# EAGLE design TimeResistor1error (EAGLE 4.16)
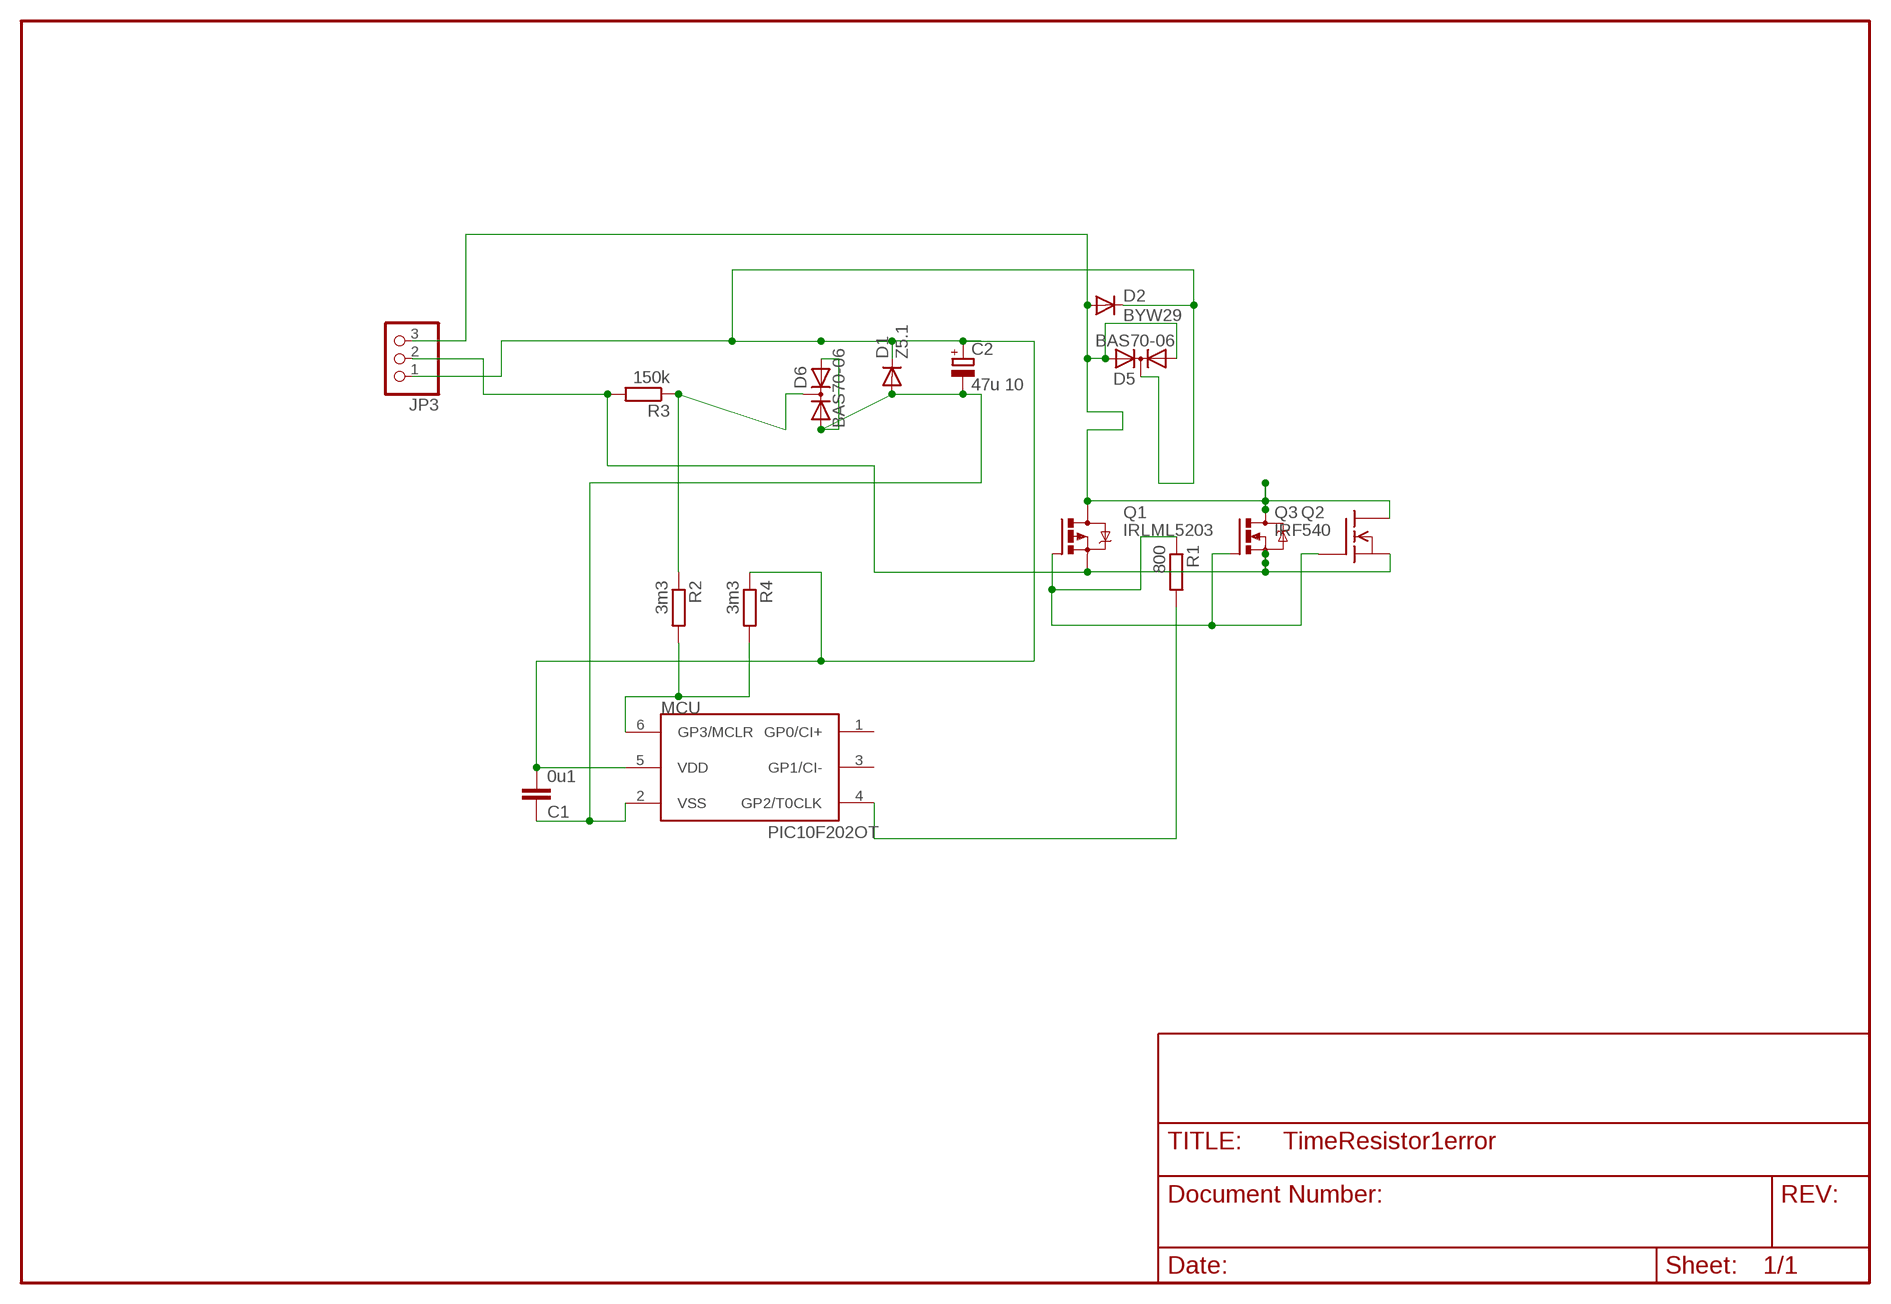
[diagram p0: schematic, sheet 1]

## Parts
C1  0u1  C-EUC1206  [C1206]
C2  47u 10  CPOL-EUSMCD  [SMC_D]
D1  Z5.1  DIODE-MINIMELF  [MINIMELF]
D2  BYW29  [DO220S]
D5  BAS70-06  [SOT23]
D6  BAS70-06  [SOT23]
JP3  PINHD-1X3  [1X03]
MCU  PIC10F202OT  [SOT23-6]
Q1  IRLML5203  [MICRO3]
Q2  N-MOSFET-SO8S  [SO-08]
Q3  IRF540  [TO220]
R1  800  R-EU_R1206  [R1206]
R2  3m3  R-EU_R1206  [R1206]
R3  150k  R-EU_R1206  [R1206]
R4  3m3  R-EU_R1206  [R1206]

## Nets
N$1: Q1.1(G) Q2.4(G) Q3.1(G) R1.1
N$2: D2.A D5.1(A1) D5.2(A2) JP3.3 Q1.3(D) Q2.5(D) Q2.7(D) Q2.8(D) Q3.2(D)
N$11: JP3.2 Q1.2(S) Q2.1(S) Q2.2(S) Q2.3(S) Q3.3(S) R3.2
N$12: MCU.6(GP3/MCLR) R2.2 R4.2
N$14: MCU.4(GP2/T0CLK) R1.2
N$17: D6.3(C) R2.1 R3.1
N$18: C1.1 C2.- D1.A D6.1(A1) D6.2(A2) MCU.2(VSS)
V2CC: C1.2 C2.+ D1.C D2.C D5.3(C) JP3.1 MCU.5(VDD) R4.1
Unconnected: MCU.1(GP0/CI+) MCU.3(GP1/CI-) Q2.6(D)

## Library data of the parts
C1 = rcl:C-EU: CAPACITOR, European symbol
C2 = rcl:CPOL-EU: POLARIZED CAPACITOR, European symbol
D1 = diode:DIODE-: DIODE
D2 = diode:BYW29: DIODE
D5 D6 = diode:BAS70-06: Silicon Schottky Diodes General-purpose diode for high-speed switching
JP3 = pinhead:PINHD-1X3: PIN HEADER
MCU = microchip-3:PIC10F2*: uPC nW 0,25/0,5k Program Flash memory Comparator
Q1 = transistor-power:IRLML5203: HEXFET P-Channel Power MOSFET
Q2 = transistor-power:N-MOSFET-SO8: N-Channel MOSFET Example: FDS7760A; N-Channel Logic Level PowerTrench® MOSFET FDS2572; N-Channel UltraFET® Trench MOSFET Source: www.fairchildsemi.com
Q3 = transistor-fet+irf7201:IRF540: N-Channel Enhancement MOSFET (HEXFET); 100V; 28A; 0,077Ohm
R1-R4 = rcl:R-EU_: RESISTOR, European symbol

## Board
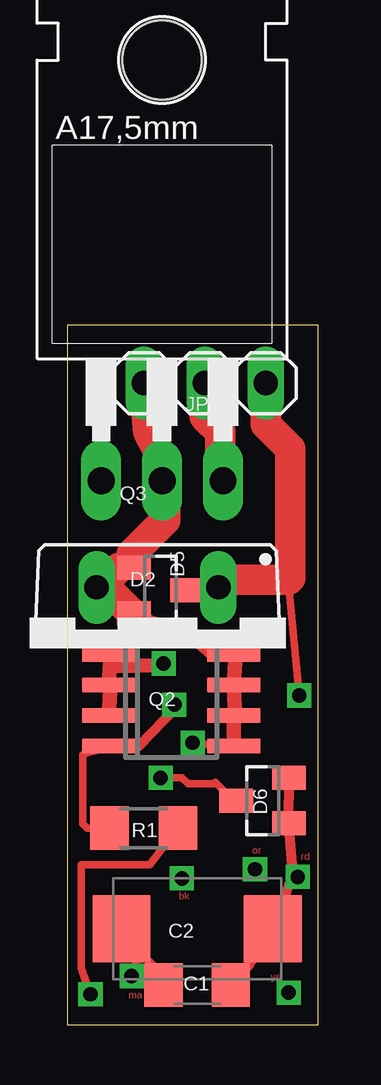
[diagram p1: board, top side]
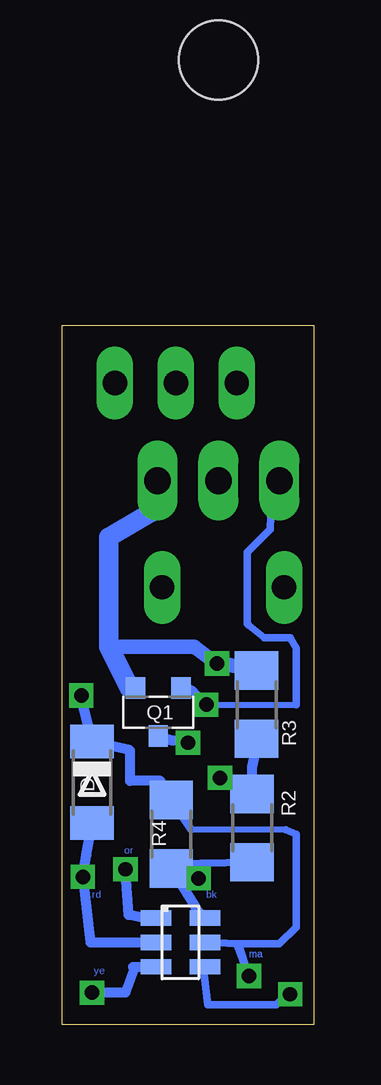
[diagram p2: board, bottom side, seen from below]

Size 10.46 x 29.14 mm. Coordinates in mm from the lower left corner, seen from the top.
Outline: 0,0 10.47,0 10.47,29.14 0,29.14 0,0
Copper layers (1*16): Top 0.035mm / dielectric 1.5mm / Bottom 0.035mm
Design rules "default": minimum track width 10mil, minimum drill 24mil, track to track 8mil, track to pad 8mil, pad to pad 8mil, via to via 8mil, smd to smd 8mil, copper to edge 40mil, drill to drill 8mil, minimum pad ring 10mil, minimum via ring 8mil, stop-mask expansion 4mil, vias tented up to drill 0mil, thermal gap 10mil

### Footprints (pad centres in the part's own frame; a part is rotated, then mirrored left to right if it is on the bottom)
C1206 = smd 1.6 x 1.8: 1 -1.4,0; 2 1.4,0
SMC_D = smd 2.4 x 2.8: + -3.15,0; - 3.15,0
MINIMELF = smd 1.4 x 1.8: A 1.7,0; C -1.7,0
DO220S = drill 1.016 long: A 2.54,-2.54; C -2.54,-2.54
SOT23 = smd 1 x 1.4: 1 -0.95,-1.1; 2 0.95,-1.1; 3 0,1.1
1X03 = drill 1.016 long: 1 -2.54,0; 2 0,0; 3 2.54,0
SOT23-6 = smd 0.635 x 1.27: 1 -1.016,-1.016; 2 0,-1.016; 3 1.016,-1.016; 4 1.016,1.016; 5 0,1.016; 6 -1.016,1.016
MICRO3 = smd 0.8 x 0.9: 1 -0.95,-1; 2 0.95,-1; 3 0,1
SO-08 = smd 0.6 x 2.2: 1 -1.905,-2.6; 2 -0.635,-2.6; 3 0.635,-2.6; 4 1.905,-2.6; 5 1.905,2.6; 6 0.635,2.6; 7 -0.635,2.6; 8 -1.905,2.6
TO220 = drill 1.118 long: 1 -2.54,-6.35; 2 0,-6.35; 3 2.54,-6.35 | hole 3.302: 0,11.176
R1206 = smd 1.6 x 1.803: 1 -1.422,0; 2 1.422,0

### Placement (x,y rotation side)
C1  5.42,1.65 180 top
C2  5.42,4 0 top
D1  9.23,10.09 270 bottom
D2  3.77,15.68 180 top
D5  3.9,18.09 270 top
D6  8.15,9.33 90 top
JP3  5.74,26.73 180 top
MCU  5.55,3.42 270 bottom
Q1  6.47,13.02 180 bottom
Q2  4.34,13.52 270 top
Q3  3.96,29.01 0 top
R1  3.2,8.19 0 top
R2  2.57,8.19 270 bottom
R3  2.38,13.33 90 bottom
R4  5.93,7.93 270 bottom

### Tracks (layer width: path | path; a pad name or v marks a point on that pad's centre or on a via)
N$1  (via drill 0.6)
  Top 0.254: 2.57,11.42 Q2.4 1.3,11.42 0.66,11.23
  Top 0.305: 0.66,11.23 0.66,8.38 0.85,8.19 1.68,8.19 1.78,8.29 R1.1 | 4.34,13.27 4.41,13.2
  Top 0.406: Q2.4 3.01,11.61 4.53,13.2 v4.47,13.33 arc254 4.41,13.2
  Bottom 0.254: 5.12,13.94 5.11,13.96 | v4.47,13.33 0.72,13.33
  Bottom 0.305: 1.36,22.73 Q3.1 1.74,22.35 1.8,20.63 2.76,19.68 2.76,16.7 2.69,16.63 2.06,16.12 0.98,16.12 0.72,15.68 0.72,13.33 | 5.12,13.94 5.45,14.15 5.55,14.22
  Bottom 0.406: v4.47,13.33 4.6,13.39 5.12,13.94 | 5.45,14.15 5.49,14.09 Q1.1
N$2  (via drill 0.6)
  Top 0.305: Q2.7 Q2.8 6.94,15.36 6.95,15.36 | 6.95,12.63 7.01,12.69 | 7.01,15.11 6.95,15.17 | Q3.2 3.96,22.54 4.09,22.41 4.15,22.47 4.15,23.24 | D5.1 2.8,19.02 2.69,18.92 2.69,19.62 | D2.A 1.3,18.22 2.12,19.04 D5.1 | 2.18,19.04 D5.1 | 2.82,17.01 2.8,17.03 D5.2 4.28,16.64 | 1.61,18.22 1.36,18.22 | 5.17,11.68 v5.23,11.74 6.88,11.55 Q2.5
  Top 0.61: Q2.5 6.95,12.63 | 7.01,12.69 Q2.7 7.01,15.11 | 4.28,16.64 5.55,15.93 6.06,15.49 6.94,15.36
  Top 1.27: JP3.3 3.39,24.7 4.15,23.24 | 4.09,22.41 4.09,21.01 2.69,19.62 | 1.36,18.22 2.18,19.04 | 2.8,17.03 1.61,18.22
  Bottom 0.305: 5.83,11.83 v5.23,11.74
  Bottom 0.406: Q1.3 5.83,11.83
N$3  (via drill 0.6)
  other vias: 4.79,6.09
N$4  (via drill 0.6)
  Bottom 0.254: v9.23,1.33 8.92,1.27 8.91,1.33
  Bottom 0.406: 7.45,2.34 7.84,1.33 8.91,1.33 8.98,1.33
N$5  (via drill 0.6)
  Bottom 0.254: v7.84,6.47 7.65,6.34 7.84,6.28
  Bottom 0.406: 6.5,4.31 7.71,4.57 7.84,6.28
N$6
  Top 0.406: 7.39,2.34 6.88,2.34
N$7
  Bottom 0.406: 7.52,2.41 6.76,2.41
N$11  (via drill 0.6)
  Top 0.305: 1.81,15.11 Q2.1 | 1.81,15.11 1.8,15.11 | 1.74,13.84 1.8,13.9 1.81,14.92 1.81,15.11 | Q3.3 6.5,22.47 6.38,22.6 | 4.03,14.98 v4.03,15.04
  Top 0.61: Q2.2 1.81,15.11 | 1.8,13.9 Q2.3 | 1.81,14.92 4.03,14.98
  Top 1.27: JP3.2 5.74,25.33 6.38,24.7 6.38,22.6
  Bottom 0.254: 7.65,13.96 Q1.2 | 6.38,21.59 Q3.3
  Bottom 0.61: 8.53,15.74 4.98,15.74 v4.03,15.04 3.96,15.04 3.94,15.07 R3.2
  Bottom 0.813: 7.65,13.96 8.53,15.74 8.53,20.32 6.38,21.59
N$12
  Bottom 0.305: MCU.6 4.53,4.5 4.91,4.88 | R4.2 6.1,6.51 6.06,6.47 5.83,6.7 R2.2
  Bottom 0.406: 4.91,4.88 R4.2
N$14  (via drill 0.6)
  Top 0.305: R1.2 3.45,6.66 0.6,6.66 0.6,2.34 v0.98,1.27
  Bottom 0.305: MCU.4 4.6,2.41 4.41,0.82 1.55,0.82 1.1,1.27 v0.98,1.27
N$17  (via drill 0.6)
  Top 0.305: D6.3 7.05,9.31 7.01,9.27 6.19,10.09 6.12,10.03 5.04,10.03 4.79,10.28 v3.9,10.28
  Bottom 0.305: 2.37,11.55 2.41,11.59 R3.1 | R2.1 2.98,9.54 v3.9,10.28
  Bottom 0.406: R2.1 2.57,10.73 2.37,11.55
N$18  (via drill 0.6)
  Top 0.406: C1.1 7.58,2.47 8.53,3.87 C2.- 9.36,6.09 v9.61,6.16 9.42,6.16 9.23,8.44 | 9.23,8.44 D6.1 | 9.23,8.44 D6.2
  Bottom 0.406: D1.A 9.47,7.06 v9.61,6.16 9.3,3.42 MCU.2
V2CC  (via drill 0.6)
  Top 0.305: C1.2 3.9,2.16 2.88,3.17 | 2.88,3.17 2.57,3.49 2.57,4.69 2.31,4.95 2.34,4.97 C2.+ | v2.69,2.03 3.14,3.42 2.88,3.17 | 9.3,18.6 9.23,18.54 9.23,18.41 9.3,18.35 9.23,18.28 v9.68,13.71 | 6.44,18.54 6.12,18.22 D2.C 6.25,18.28 6.06,18.09 D5.3
  Top 1.27: JP3.1 8.28,25.01 9.3,24 9.3,18.6 | 9.23,18.54 6.44,18.54
  Bottom 0.254: 1.17,8.12 5.11,8.12 | 6.38,10.15 6.06,9.33 R4.1
  Bottom 0.305: MCU.5 3.14,3.36 v2.69,2.03 3.2,3.36 1.42,3.36 0.72,4.06 0.72,7.93 1.17,8.12 | 5.11,8.12 R4.1
  Bottom 0.406: 6.38,10.15 7.65,10.15 7.65,11.42 D1.C 9.68,13.65 v9.68,13.71

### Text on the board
Top: or | rd | bk | ye | ma
Bottom: or | bk | rd | ma | ma | ye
